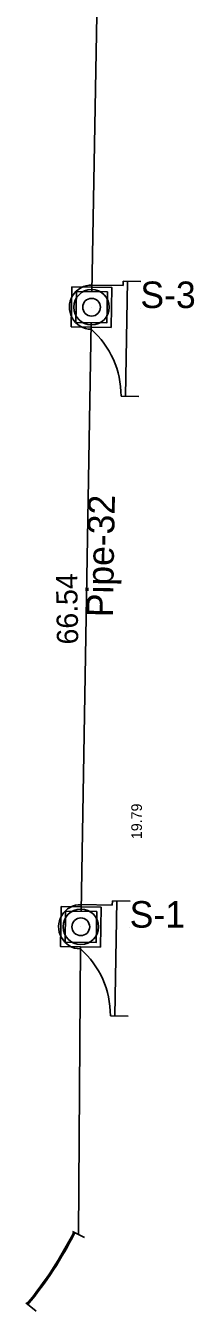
# Model space of a CAD drawing. Extents: x 925371 to 925937, y 853654 to 858024.
# Drawn here: x 925746.4 to 925765.4, y 853654.1 to 853799.4 of the extents above; entities that cross this region are included whole.
import ezdxf

# ---------------------------------------------------------------- set-up
doc = ezdxf.new("R2010")
doc.units = 0
for name, color, linetype in [('GPKDrBack_dp', 7, 'Continuous'), ('GPKDrBottom_dp', 7, 'Continuous'), ('GPKDrCellIns_dp', 7, 'Continuous'), ('GPKDrCentroid_dp', 7, 'Continuous'), ('GPKDrFront_dp', 7, 'Continuous'), ('GPKDrPipe_dp', 7, 'Continuous'), ('GPKDrPipeCir_dp', 7, 'Continuous'), ('InletBottomP', 7, 'Continuous'), ('InletCurb', 7, 'Continuous'), ('NonPlottingEle_dp', 7, 'Continuous'), ('PipeCulvert', 7, 'Continuous'), ('PipeCulvertSS', 7, 'Continuous'), ('Trench', 7, 'Continuous')]:
    doc.layers.add(name, color=color, linetype=linetype)

msp = doc.modelspace()

# ---------------------------------------------------------------- linework, layer by layer
at = {"layer": 'GPKDrBack_dp'}
for p, q in [((925751.34, 853767.6), (925751.34, 853767.6)), ((925752.09, 853767.58), (925752.09, 853767.58)), ((925750.14, 853697.57), (925750.14, 853697.57)), ((925750.88, 853697.55), (925750.88, 853697.55))]:
    msp.add_line(p, q, dxfattribs=at)
at = {"layer": 'GPKDrBottom_dp'}
for p, q in [((925752.13, 853769.33), (925752.13, 853769.33)), ((925752.46, 853768.99), (925752.46, 853768.99)), ((925753.88, 853769.55), (925753.88, 853769.55)), ((925753.88, 853769.3), (925753.88, 853769.3)), ((925755.28, 853768.94), (925755.28, 853768.94)), ((925755.63, 853769.27), (925755.63, 853769.27)), ((925751.84, 853767.59), (925751.84, 853767.59)), ((925752.09, 853767.58), (925752.09, 853767.58)), ((925753.84, 853767.55), (925753.84, 853767.55)), ((925753.84, 853767.55), (925753.84, 853767.55)), ((925755.59, 853767.52), (925755.59, 853767.52)), ((925755.84, 853767.52), (925755.84, 853767.52)), ((925752.06, 853765.83), (925752.06, 853765.83)), ((925752.4, 853766.16), (925752.4, 853766.16)), ((925753.81, 853765.8), (925753.81, 853765.8)), ((925755.23, 853766.11), (925755.23, 853766.11)), ((925755.56, 853765.77), (925755.56, 853765.77)), ((925753.81, 853765.55), (925753.81, 853765.55)), ((925750.92, 853699.3), (925750.92, 853699.3)), ((925751.25, 853698.96), (925751.25, 853698.96)), ((925752.67, 853699.52), (925752.67, 853699.52)), ((925752.67, 853699.27), (925752.67, 853699.27)), ((925754.07, 853698.91), (925754.07, 853698.91)), ((925754.42, 853699.24), (925754.42, 853699.24)), ((925750.63, 853697.56), (925750.63, 853697.56)), ((925750.88, 853697.55), (925750.88, 853697.55)), ((925752.63, 853697.52), (925752.63, 853697.52)), ((925752.63, 853697.52), (925752.63, 853697.52)), ((925754.38, 853697.49), (925754.38, 853697.49)), ((925754.63, 853697.49), (925754.63, 853697.49)), ((925751.2, 853696.13), (925751.2, 853696.13)), ((925754.02, 853696.08), (925754.02, 853696.08)), ((925750.85, 853695.8), (925750.85, 853695.8)), ((925752.6, 853695.77), (925752.6, 853695.77)), ((925752.6, 853695.52), (925752.6, 853695.52)), ((925754.35, 853695.74), (925754.35, 853695.74))]:
    msp.add_line(p, q, dxfattribs=at)
at = {"layer": 'GPKDrCellIns_dp'}
for p, q in [((925753.84, 853767.55), (925753.84, 853767.55)), ((925759.34, 853767.45), (925759.34, 853767.45)), ((925752.63, 853697.52), (925752.63, 853697.52)), ((925758.13, 853697.42), (925758.13, 853697.42))]:
    msp.add_line(p, q, dxfattribs=at)
at = {"layer": 'GPKDrCentroid_dp'}
for p, q in [((925753.84, 853767.55), (925753.84, 853767.55)), ((925752.63, 853697.52), (925752.63, 853697.52))]:
    msp.add_line(p, q, dxfattribs=at)
at = {"layer": 'GPKDrFront_dp'}
for p, q in [((925755.59, 853767.52), (925755.59, 853767.52)), ((925759.34, 853767.45), (925759.34, 853767.45)), ((925754.38, 853697.49), (925754.38, 853697.49)), ((925758.13, 853697.42), (925758.13, 853697.42))]:
    msp.add_line(p, q, dxfattribs=at)
at = {"layer": 'GPKDrPipe_dp'}
for p, q in [((925752.48, 853769.01), (925752.48, 853769.01)), ((925753.13, 853769.42), (925753.13, 853769.42)), ((925753.88, 853769.55), (925753.88, 853769.55)), ((925753.88, 853769.3), (925753.88, 853769.3)), ((925754.68, 853769.37), (925754.68, 853769.37)), ((925755.3, 853768.92), (925755.3, 853768.92)), ((925751.84, 853767.59), (925751.84, 853767.59)), ((925752.03, 853768.39), (925752.03, 853768.39)), ((925752.09, 853767.58), (925752.09, 853767.58)), ((925755.59, 853767.52), (925755.59, 853767.52)), ((925755.71, 853768.27), (925755.71, 853768.27)), ((925755.84, 853767.52), (925755.84, 853767.52)), ((925751.98, 853766.83), (925751.98, 853766.83)), ((925752.38, 853766.18), (925752.38, 853766.18)), ((925753.01, 853765.74), (925753.01, 853765.74)), ((925753.81, 853765.8), (925753.81, 853765.8)), ((925754.56, 853765.69), (925754.56, 853765.69)), ((925755.21, 853766.09), (925755.21, 853766.09)), ((925755.66, 853766.71), (925755.66, 853766.71)), ((925753.81, 853765.55), (925753.81, 853765.55)), ((925751.27, 853698.98), (925751.27, 853698.98)), ((925751.92, 853699.39), (925751.92, 853699.39)), ((925752.67, 853699.52), (925752.67, 853699.52)), ((925752.67, 853699.27), (925752.67, 853699.27)), ((925753.47, 853699.34), (925753.47, 853699.34)), ((925754.09, 853698.89), (925754.09, 853698.89)), ((925750.63, 853697.56), (925750.63, 853697.56)), ((925750.82, 853698.36), (925750.82, 853698.36)), ((925750.88, 853697.55), (925750.88, 853697.55)), ((925754.38, 853697.49), (925754.38, 853697.49)), ((925754.5, 853698.24), (925754.5, 853698.24)), ((925754.63, 853697.49), (925754.63, 853697.49)), ((925750.77, 853696.8), (925750.77, 853696.8)), ((925751.18, 853696.15), (925751.18, 853696.15)), ((925754, 853696.06), (925754, 853696.06)), ((925754.45, 853696.68), (925754.45, 853696.68)), ((925751.8, 853695.71), (925751.8, 853695.71)), ((925752.6, 853695.77), (925752.6, 853695.77)), ((925752.6, 853695.52), (925752.6, 853695.52)), ((925753.35, 853695.66), (925753.35, 853695.66))]:
    msp.add_line(p, q, dxfattribs=at)
at = {"layer": 'GPKDrPipeCir_dp'}
for centre in [(925753.84, 853767.55), (925752.63, 853697.52)]:
    msp.add_circle(centre, 2, dxfattribs=at)
at = {"layer": 'InletBottomP'}
for points in [[(925751.63, 853769.84), (925751.55, 853765.34), (925756.05, 853765.26), (925756.13, 853769.76)], [(925755.63, 853769.27), (925752.13, 853769.33), (925752.06, 853765.83), (925755.56, 853765.77)], [(925750.43, 853699.81), (925750.34, 853695.31), (925754.84, 853695.23), (925754.92, 853699.73)], [(925754.42, 853699.24), (925750.92, 853699.3), (925750.85, 853695.8), (925754.35, 853695.74)]]:
    msp.add_lwpolyline(points, close=True, dxfattribs=at)
at = {"layer": 'InletCurb'}
for p, q in [((925757.39, 853769.99), (925753.89, 853770.05)), ((925757.4, 853770.49), (925757.39, 853769.99)), ((925759.4, 853770.45), (925757.4, 853770.49)), ((925757.66, 853757.48), (925757.9, 853770.48)), ((925757.16, 853757.49), (925759.16, 853757.46)), ((925756.19, 853700.46), (925756.18, 853699.96)), ((925758.19, 853700.42), (925756.19, 853700.46)), ((925756.45, 853687.45), (925756.69, 853700.45)), ((925756.18, 853699.96), (925752.68, 853700.02)), ((925755.96, 853687.46), (925757.95, 853687.42))]:
    msp.add_line(p, q, dxfattribs=at)
for centre in [(925753.84, 853767.55), (925752.63, 853697.52)]:
    msp.add_circle(centre, 1, dxfattribs=at)
for centre, radius, start, end in [((925753.84, 853767.55), 2.5, 88.9741, 268.9741), ((925747.16, 853757.57), 10, 359.5458, 48.4363), ((925752.63, 853697.52), 2.5, 88.9741, 268.9741), ((925745.96, 853687.54), 10, 359.5458, 48.4363)]:
    msp.add_arc(centre, radius, start, end, dxfattribs=at)
at = {"layer": 'PipeCulvert'}
for p, q in [((925753.88, 853769.3), (925755.17, 853842.03)), ((925752.67, 853699.27), (925753.81, 853765.8))]:
    msp.add_line(p, q, dxfattribs=at)
at = {"layer": 'PipeCulvertSS'}
msp.add_line((925752.36, 853662.75), (925752.59, 853695.27), dxfattribs=at)
at = {"layer": 'Trench'}
for p, q in [((925751.69, 853663.08), (925753.03, 853662.41)), ((925746.43, 853655.02), (925747.59, 853654.06))]:
    msp.add_line(p, q, dxfattribs=at)
for radius in [43.67, 43.81]:
    msp.add_arc((925712.85, 853682.67), radius, 320.5307, 333.2454, dxfattribs=at)

# ---------------------------------------------------------------- texts
at = {"layer": 'NonPlottingEle_dp'}
for s, p in [('S-3', (925759.34, 853767.45)), ('S-1', (925758.13, 853697.42))]:
    msp.add_text(s, height=3, dxfattribs=at).set_placement(p)
for s, height, rotation, p in [('Pipe-32', 3, 89.0124, (925756.24, 853732.49)), ('66.54', 2.4, 90.9741, (925752.35, 853729.45)), ('19.79', 1.2, 90, (925759.52, 853707.43))]:
    msp.add_text(s, height=height, rotation=rotation, dxfattribs=at).set_placement(p)

doc.saveas('drawing.dxf')
